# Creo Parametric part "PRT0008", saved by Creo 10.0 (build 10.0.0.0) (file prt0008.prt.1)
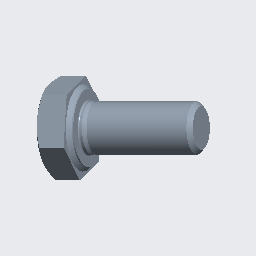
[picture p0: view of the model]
Units: millimeter Newton Second (mmNs); MM, TONNE, SECS

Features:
  1. coordinate system "SCHRAUBEN"
  2. imported feature "Import-ke ID 4"

Surfaces: 14 cone, 11 plane, 6 cylinder, 2 torus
